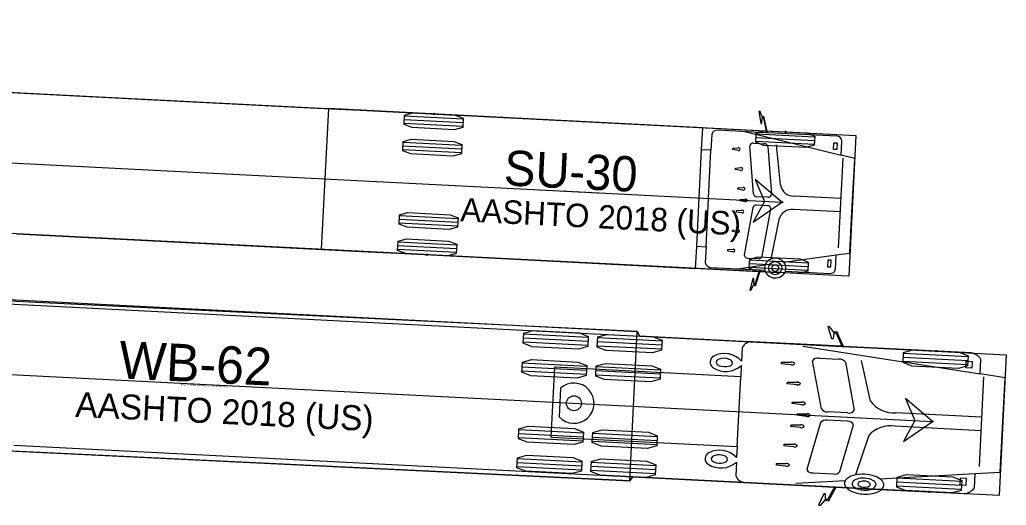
# Model space of a CAD drawing. Extents: x 260275 to 261282, y 610916 to 614143.
# Drawn here: x 261226.4 to 261282.5, y 611586.9 to 611614.4 of the extents above; entities that cross this region are included whole.
import ezdxf

# ---------------------------------------------------------------- set-up
doc = ezdxf.new("R2010")
doc.units = 0
doc.layers.add('UT_X_Water_Cells', color=7, linetype='Continuous')

msp = doc.modelspace()

# ---------------------------------------------------------------- linework, layer by layer
at = {"layer": 'UT_X_Water_Cells'}
for p, q in [((261066.343, 611614.434), (261269.731, 611604.069)), ((261251.604, 611608.581), (261248.275, 611608.751)), ((261251.615, 611608.789), (261248.286, 611608.959)), ((261251.594, 611608.373), (261248.265, 611608.543)), ((261267.627, 611608.081), (261273.094, 611606.736)), ((261271.568, 611607.354), (261268.239, 611607.524)), ((261271.578, 611607.563), (261268.249, 611607.732)), ((261271.589, 611607.771), (261268.26, 611607.94)), ((261251.517, 611606.875), (261248.188, 611607.044)), ((261251.528, 611607.083), (261248.199, 611607.253)), ((261251.539, 611607.291), (261248.21, 611607.461)), ((261264.884, 611601.566), (261265.164, 611607.051)), ((261265.415, 611601.539), (261265.695, 611607.024)), ((261266.938, 611607.056), (261266.942, 611607.139)), ((261267.236, 611607.005), (261266.938, 611607.056)), ((261266.942, 611607.139), (261267.244, 611607.159)), ((261268.116, 611604.541), (261267.902, 611607.25)), ((261268.113, 611607.421), (261268.729, 611607.389)), ((261268.923, 611607.228), (261269.137, 611604.519)), ((261269.651, 611605.056), (261269.422, 611607.334)), ((261272.654, 611607.07), (261272.673, 611607.448)), ((261272.848, 611607.06), (261272.654, 611607.07)), ((261272.673, 611607.448), (261272.867, 611607.438)), ((261272.867, 611607.438), (261272.848, 611607.06)), ((261272.949, 611601.482), (261273.209, 611606.58)), ((261267.091, 611605.93), (261267.096, 611606.012)), ((261267.403, 611605.879), (261267.091, 611605.93)), ((261267.096, 611606.012), (261267.41, 611606.033)), ((261267.217, 611604.805), (261267.221, 611604.887)), ((261267.514, 611604.754), (261267.217, 611604.805)), ((261267.221, 611604.887), (261267.522, 611604.908)), ((261267.352, 611604.149), (261267.356, 611604.231)), ((261267.649, 611604.098), (261267.352, 611604.149)), ((261267.356, 611604.231), (261267.657, 611604.252)), ((261268.926, 611604.348), (261268.31, 611604.379)), ((261273.091, 611604.281), (261270.427, 611604.417)), ((261267.151, 611603.51), (261267.155, 611603.592)), ((261267.155, 611603.592), (261267.456, 611603.613)), ((261268.076, 611603.763), (261267.588, 611601.09)), ((261268.902, 611603.873), (261268.286, 611603.904)), ((261268.606, 611601.008), (261269.094, 611603.681)), ((261273.052, 611603.516), (261270.388, 611603.652)), ((261251.316, 611602.922), (261247.987, 611603.091)), ((261251.326, 611603.13), (261247.997, 611603.299)), ((261267.448, 611603.459), (261267.151, 611603.51)), ((261269.551, 611603.095), (261269.089, 611600.84)), ((261251.305, 611602.713), (261247.976, 611602.883)), ((261266.912, 611602.403), (261266.916, 611602.486)), ((261266.916, 611602.486), (261267.217, 611602.506)), ((261267.209, 611602.352), (261266.912, 611602.403)), ((261251.229, 611601.215), (261247.9, 611601.385)), ((261251.239, 611601.423), (261247.91, 611601.593)), ((261251.25, 611601.632), (261247.921, 611601.801)), ((261266.645, 611601.298), (261266.649, 611601.381)), ((261266.649, 611601.381), (261266.95, 611601.401)), ((261266.942, 611601.247), (261266.645, 611601.298)), ((261267.78, 611600.899), (261268.396, 611600.867)), ((261271.224, 611600.613), (261267.895, 611600.783)), ((261269.839, 611600.657), (261272.805, 611601.073)), ((261272.334, 611600.786), (261272.315, 611600.408)), ((261272.528, 611600.776), (261272.334, 611600.786)), ((261267.23, 611600.291), (261268.764, 611600.506)), ((261271.203, 611600.197), (261267.874, 611600.367)), ((261271.214, 611600.405), (261267.885, 611600.575)), ((261272.315, 611600.408), (261272.508, 611600.398)), ((261272.508, 611600.398), (261272.528, 611600.776)), ((261269.929, 611600.154), (261272.448, 611600.025)), ((261137.985, 611598.767), (261278.274, 611591.618)), ((261258.713, 611596.159), (261255.051, 611596.345)), ((261258.724, 611596.388), (261255.062, 611596.574)), ((261262.919, 611596.175), (261259.257, 611596.361)), ((261272.689, 611596.668), (261272.674, 611596.689)), ((261272.687, 611596.642), (261272.689, 611596.668)), ((261258.701, 611595.93), (261255.039, 611596.117)), ((261262.896, 611595.717), (261259.234, 611595.903)), ((261262.907, 611595.946), (261259.245, 611596.132)), ((261267.474, 611595.822), (261267.434, 611595.048)), ((261270.921, 611595.897), (261280.988, 611594.319)), ((261271.839, 611595.215), (261272.968, 611595.157)), ((261280.285, 611595.062), (261276.623, 611595.248)), ((261280.296, 611595.291), (261276.635, 611595.477)), ((261258.629, 611594.511), (261254.967, 611594.698)), ((261258.641, 611594.74), (261254.979, 611594.926)), ((261262.835, 611594.527), (261259.173, 611594.713)), ((261269.703, 611594.899), (261269.707, 611594.981)), ((261270.25, 611594.835), (261269.703, 611594.899)), ((261269.707, 611594.981), (261270.258, 611594.989)), ((261271.966, 611592.329), (261271.459, 611595.052)), ((261273.33, 611594.987), (261273.837, 611592.263)), ((261274.756, 611592.779), (261274.239, 611595.073)), ((261280.273, 611594.833), (261276.611, 611595.019)), ((261280.169, 611594.671), (261280.189, 611595.049)), ((261280.525, 611594.653), (261280.169, 611594.671)), ((261280.189, 611595.049), (261280.544, 611595.031)), ((261280.544, 611595.031), (261280.525, 611594.653)), ((261258.617, 611594.282), (261254.955, 611594.469)), ((261262.812, 611594.069), (261259.15, 611594.255)), ((261262.823, 611594.298), (261259.162, 611594.484)), ((261267.187, 611590.192), (261267.389, 611594.161)), ((261280.946, 611589.059), (261281.205, 611594.158)), ((261282.132, 611588.733), (261282.405, 611594.096)), ((261257.146, 611593.502), (261257.064, 611591.888)), ((261270.031, 611593.764), (261270.035, 611593.846)), ((261270.603, 611593.699), (261270.031, 611593.764)), ((261270.035, 611593.846), (261270.611, 611593.853)), ((261270.308, 611592.631), (261270.313, 611592.713)), ((261270.855, 611592.567), (261270.308, 611592.631)), ((261270.313, 611592.713), (261270.863, 611592.721)), ((261270.584, 611591.968), (261270.588, 611592.05)), ((261271.131, 611591.904), (261270.584, 611591.968)), ((261270.588, 611592.05), (261271.138, 611592.058)), ((261273.458, 611592.101), (261272.328, 611592.158)), ((261281.088, 611591.858), (261276.203, 611592.106)), ((261270.242, 611591.336), (261270.247, 611591.418)), ((261270.79, 611591.272), (261270.242, 611591.336)), ((261270.247, 611591.418), (261270.797, 611591.426)), ((261271.927, 611591.551), (261271.146, 611588.893)), ((261273.434, 611591.626), (261272.304, 611591.683)), ((261273.013, 611588.768), (261273.794, 611591.426)), ((261281.05, 611591.093), (261276.164, 611591.342)), ((261258.437, 611590.733), (261254.775, 611590.919)), ((261258.448, 611590.962), (261254.786, 611591.148)), ((261262.631, 611590.519), (261258.969, 611590.706)), ((261262.643, 611590.748), (261258.981, 611590.935)), ((261274.656, 611590.819), (261273.905, 611588.579)), ((261258.425, 611590.504), (261254.763, 611590.69)), ((261262.62, 611590.291), (261258.958, 611590.477)), ((261269.852, 611590.237), (261269.856, 611590.32)), ((261270.399, 611590.173), (261269.852, 611590.237)), ((261269.856, 611590.32), (261270.407, 611590.328)), ((261258.341, 611588.856), (261254.679, 611589.042)), ((261258.353, 611589.085), (261254.691, 611589.271)), ((261258.364, 611589.314), (261254.703, 611589.5)), ((261262.547, 611588.872), (261258.885, 611589.058)), ((261262.559, 611589.1), (261258.897, 611589.287)), ((261267.142, 611589.306), (261267.103, 611588.531)), ((261269.41, 611589.141), (261269.414, 611589.223)), ((261269.957, 611589.077), (261269.41, 611589.141)), ((261269.414, 611589.223), (261269.965, 611589.231)), ((261262.536, 611588.643), (261258.874, 611588.829)), ((261271.507, 611588.692), (261272.636, 611588.635)), ((261275.286, 611588.364), (261280.7, 611588.655)), ((261270.524, 611588.107), (261273.324, 611588.258)), ((261279.913, 611587.759), (261276.251, 611587.945)), ((261279.925, 611587.988), (261276.263, 611588.174)), ((261279.937, 611588.216), (261276.275, 611588.403)), ((261279.85, 611588.388), (261279.83, 611588.01)), ((261279.83, 611588.01), (261280.186, 611587.991)), ((261280.205, 611588.37), (261279.85, 611588.388)), ((261280.186, 611587.991), (261280.205, 611588.37)), ((261275.389, 611587.759), (261280.084, 611587.521)), ((261272.206, 611587.16), (261272.188, 611587.141)), ((261272.206, 611587.186), (261272.206, 611587.16))]:
    msp.add_line(p, q, dxfattribs=at)
for points in [[(261156.1, 611613.904), (261198.699, 611611.699), (261273.93, 611607.86), (261273.523, 611599.87), (261188.635, 611604.191), (261146.014, 611606.327)], [(261223.331, 611610.44), (261226.66, 611610.27), (261229.989, 611610.1), (261233.317, 611609.931), (261236.646, 611609.761), (261239.975, 611609.591), (261243.304, 611609.421), (261246.632, 611609.252), (261249.961, 611609.082)], [(261223.333, 611610.439), (261226.662, 611610.269), (261229.99, 611610.099), (261233.319, 611609.93), (261236.648, 611609.76), (261239.976, 611609.59), (261243.305, 611609.421), (261246.634, 611609.251), (261249.963, 611609.081), (261253.291, 611608.912), (261256.62, 611608.742), (261259.949, 611608.572), (261263.278, 611608.403), (261266.606, 611608.233), (261269.935, 611608.064)], [(261265.741, 611607.922), (261265.695, 611607.027), (261265.691, 611607.024), (261265.165, 611607.051), (261265.165, 611607.062), (261265.228, 611608.304), (261243.969, 611609.387), (261243.765, 611605.393), (261243.561, 611601.398), (261264.82, 611600.314), (261264.884, 611601.555), (261264.885, 611601.566), (261265.412, 611601.539), (261265.415, 611601.536), (261265.369, 611600.641)], [(261268.651, 611608.91), (261268.604, 611608.913), (261268.603, 611608.913), (261268.487, 611609.214), (261268.422, 611609.218), (261268.422, 611609.215), (261268.528, 611608.553), (261268.529, 611608.549), (261268.584, 611608.547), (261268.585, 611608.549), (261268.61, 611608.866), (261268.61, 611608.866), (261268.654, 611608.863)], [(261268.674, 611608.851), (261268.674, 611608.851), (261268.851, 611608.023), (261268.839, 611608.019), (261266.069, 611608.161)], [(261272.845, 611607.815), (261268.917, 611608.015), (261268.906, 611608.023), (261268.722, 611608.865), (261268.722, 611608.866)], [(261272.764, 611600.263), (261272.805, 611601.069), (261272.81, 611601.074), (261273.587, 611601.183), (261273.592, 611601.225), (261273.726, 611603.865), (261273.861, 611606.505), (261273.861, 611606.547), (261273.098, 611606.735), (261273.094, 611606.74), (261273.135, 611607.546)], [(261269.731, 611604.069), (261268.209, 611605.365), (261268.733, 611604.12), (261268.085, 611602.934), (261269.731, 611604.069)], [(261226.252, 611602.281), (261229.581, 611602.111), (261232.91, 611601.941), (261236.239, 611601.771), (261239.567, 611601.601), (261242.896, 611601.432), (261246.225, 611601.262), (261249.554, 611601.092)], [(261226.253, 611602.279), (261229.582, 611602.11), (261232.911, 611601.94), (261236.24, 611601.77), (261239.569, 611601.601), (261242.897, 611601.431), (261246.226, 611601.261), (261249.555, 611601.092), (261252.884, 611600.922), (261256.213, 611600.752), (261259.541, 611600.583), (261262.87, 611600.413), (261266.199, 611600.244), (261269.528, 611600.074)], [(261170.375, 611601.234), (261181.049, 611600.761), (261202.389, 611599.731), (261261.501, 611596.733), (261261.634, 611596.472), (261282.472, 611595.409), (261282.066, 611587.42), (261261.234, 611588.48), (261261.092, 611588.243), (261197.652, 611591.285), (261176.331, 611592.251), (261165.672, 611592.71)], [(261265.672, 611600.371), (261268.442, 611600.229), (261268.454, 611600.224), (261268.193, 611599.419), (261268.193, 611599.419)], [(261268.239, 611599.399), (261268.239, 611599.4), (261268.508, 611600.219), (261268.52, 611600.225), (261268.748, 611600.214)], [(261268.172, 611599.409), (261268.128, 611599.41), (261268.127, 611599.411), (261268.135, 611599.728), (261268.135, 611599.731), (261268.079, 611599.733), (261268.078, 611599.731), (261267.906, 611599.083), (261267.905, 611599.08), (261267.97, 611599.076), (261268.117, 611599.364), (261268.117, 611599.364), (261268.164, 611599.363)], [(261213.219, 611590.573), (261213.218, 611590.55), (261261.092, 611588.243), (261261.296, 611592.488), (261261.501, 611596.733), (261213.627, 611599.04), (261213.626, 611599.018)], [(261223.157, 611598.432), (261226.49, 611598.262), (261229.823, 611598.092), (261233.156, 611597.922), (261236.488, 611597.753), (261239.821, 611597.583), (261243.154, 611597.413), (261246.486, 611597.243), (261249.819, 611597.073), (261253.151, 611596.903), (261256.484, 611596.733), (261259.816, 611596.564), (261263.148, 611596.394), (261266.481, 611596.224), (261269.813, 611596.054), (261273.145, 611595.884), (261276.478, 611595.715), (261278.477, 611595.613)], [(261272.761, 611596.684), (261272.674, 611596.689), (261272.448, 611596.996), (261272.328, 611597.002), (261272.552, 611596.328), (261272.654, 611596.323), (261272.687, 611596.642), (261272.768, 611596.638)], [(261272.805, 611596.624), (261272.805, 611596.624), (261273.123, 611595.885), (261268.048, 611596.143)], [(261280.49, 611595.51), (261273.223, 611595.88), (261272.892, 611596.637)], [(261267.421, 611594.791), (261267.389, 611594.161), (261256.803, 611594.7), (261256.601, 611590.731), (261267.187, 611590.192), (261267.155, 611589.563)], [(261282.132, 611588.733), (261282.405, 611594.096), (261280.988, 611594.319), (261281.029, 611595.132)], [(261278.274, 611591.618), (261276.751, 611592.914), (261277.275, 611591.669), (261276.627, 611590.483), (261278.274, 611591.618)], [(261226.091, 611590.272), (261229.422, 611590.102), (261232.754, 611589.932), (261236.086, 611589.763), (261239.418, 611589.593), (261242.75, 611589.423), (261246.082, 611589.253), (261249.414, 611589.083), (261252.746, 611588.914), (261256.078, 611588.744), (261259.41, 611588.574), (261262.742, 611588.404), (261266.075, 611588.234), (261269.407, 611588.064), (261272.739, 611587.895), (261276.071, 611587.725), (261278.071, 611587.623)], [(261280.659, 611587.842), (261280.7, 611588.655), (261282.12, 611588.732)], [(261267.642, 611588.153), (261272.717, 611587.895), (261272.325, 611587.192), (261272.325, 611587.192)], [(261272.41, 611587.171), (261272.816, 611587.89), (261273.389, 611587.861)], [(261272.287, 611587.183), (261272.206, 611587.186), (261272.206, 611587.507), (261272.103, 611587.512), (261271.812, 611586.864), (261271.932, 611586.858), (261272.188, 611587.141), (261272.275, 611587.137)]]:
    msp.add_lwpolyline(points, dxfattribs=at)
for points in [[(261251.618, 611608.841), (261251.591, 611608.321), (261251.117, 611608.188), (261248.72, 611608.311), (261248.262, 611608.491), (261248.289, 611609.01), (261248.763, 611609.143), (261251.16, 611609.021)], [(261271.592, 611607.822), (261271.565, 611607.303), (261271.091, 611607.17), (261268.694, 611607.292), (261268.236, 611607.473), (261268.263, 611607.992), (261268.737, 611608.125), (261271.134, 611608.002)], [(261251.541, 611607.342), (261251.515, 611606.823), (261251.041, 611606.69), (261248.644, 611606.813), (261248.186, 611606.993), (261248.212, 611607.512), (261248.686, 611607.645), (261251.083, 611607.523)], [(261269.731, 611604.069), (261268.209, 611605.365), (261268.733, 611604.12), (261268.085, 611602.934)], [(261251.329, 611603.181), (261251.303, 611602.662), (261250.829, 611602.529), (261248.432, 611602.651), (261247.974, 611602.832), (261248, 611603.351), (261248.474, 611603.484), (261250.871, 611603.361)], [(261251.253, 611601.683), (261251.226, 611601.164), (261250.752, 611601.031), (261248.355, 611601.153), (261247.897, 611601.334), (261247.924, 611601.853), (261248.398, 611601.986), (261250.795, 611601.863)], [(261271.227, 611600.665), (261271.2, 611600.146), (261270.726, 611600.013), (261268.329, 611600.135), (261267.871, 611600.315), (261267.898, 611600.835), (261268.372, 611600.967), (261270.769, 611600.845)], [(261258.727, 611596.445), (261258.698, 611595.874), (261258.177, 611595.728), (261255.54, 611595.862), (261255.036, 611596.06), (261255.065, 611596.631), (261255.587, 611596.777), (261258.223, 611596.643)], [(261262.922, 611596.231), (261262.893, 611595.66), (261262.371, 611595.514), (261259.735, 611595.648), (261259.231, 611595.846), (261259.26, 611596.418), (261259.781, 611596.564), (261262.418, 611596.43)], [(261280.299, 611595.347), (261280.27, 611594.776), (261279.749, 611594.63), (261277.112, 611594.764), (261276.608, 611594.962), (261276.637, 611595.534), (261277.159, 611595.68), (261279.795, 611595.546)], [(261258.643, 611594.797), (261258.614, 611594.226), (261258.093, 611594.08), (261255.456, 611594.214), (261254.952, 611594.412), (261254.981, 611594.983), (261255.503, 611595.129), (261258.139, 611594.995)], [(261262.838, 611594.584), (261262.809, 611594.012), (261262.287, 611593.866), (261259.651, 611594), (261259.147, 611594.199), (261259.176, 611594.77), (261259.697, 611594.916), (261262.334, 611594.782)], [(261278.274, 611591.618), (261276.751, 611592.914), (261277.275, 611591.669), (261276.627, 611590.483)], [(261258.451, 611591.018), (261258.422, 611590.447), (261257.901, 611590.301), (261255.264, 611590.435), (261254.76, 611590.634), (261254.789, 611591.205), (261255.311, 611591.351), (261257.947, 611591.217)], [(261262.646, 611590.805), (261262.617, 611590.234), (261262.095, 611590.088), (261259.459, 611590.222), (261258.955, 611590.42), (261258.984, 611590.991), (261259.505, 611591.137), (261262.142, 611591.003)], [(261258.367, 611589.371), (261258.338, 611588.799), (261257.817, 611588.653), (261255.18, 611588.787), (261254.676, 611588.986), (261254.705, 611589.557), (261255.227, 611589.703), (261257.863, 611589.569)], [(261262.562, 611589.157), (261262.533, 611588.586), (261262.011, 611588.44), (261259.375, 611588.574), (261258.871, 611588.772), (261258.9, 611589.344), (261259.421, 611589.49), (261262.058, 611589.355)], [(261279.939, 611588.273), (261279.91, 611587.702), (261279.389, 611587.556), (261276.752, 611587.69), (261276.248, 611587.888), (261276.278, 611588.459), (261276.799, 611588.606), (261279.436, 611588.471)]]:
    msp.add_lwpolyline(points, close=True, dxfattribs=at)
for centre, radius in [((261249.961, 611609.082), 0.0417), ((261269.935, 611608.064), 0.0417), ((261269.731, 611604.069), 0.0417), ((261249.554, 611601.092), 0.0417), ((261269.346, 611600.329), 0.374), ((261269.346, 611600.329), 0.193), ((261269.528, 611600.074), 0.0417), ((261278.477, 611595.613), 0.0417), ((261257.912, 611592.651), 0.424), ((261278.274, 611591.618), 0.0417), ((261278.071, 611587.623), 0.0417)]:
    msp.add_circle(centre, radius, dxfattribs=at)
for centre, radius, start, end in [((261268.686, 611608.887), 0.0418, 329.5734, 146.5883), ((261268.686, 611608.893), 0.0434, 222.4952, 253.168), ((261266.052, 611607.838), 0.323, 87.0815, 164.9299), ((261272.853, 611607.534), 0.282, 2.6299, 91.7093), ((261267.259, 611607.093), 0.0909, 255.3624, 349.5976), ((261267.257, 611607.069), 0.091, 4.601, 98.7649), ((261268.086, 611607.238), 0.184, 81.6176, 176.4889), ((261268.733, 611607.197), 0.193, 9.2239, 91.1384), ((261267.412, 611605.967), 0.0909, 255.3624, 349.5976), ((261267.411, 611605.943), 0.091, 4.601, 98.7649), ((261267.537, 611604.842), 0.0909, 255.3624, 349.5976), ((261267.536, 611604.818), 0.091, 4.601, 98.7649), ((261270.412, 611605.189), 0.773, 189.9719, 271.0561), ((261267.672, 611604.186), 0.091, 255.398, 349.5619), ((261267.671, 611604.162), 0.091, 4.601, 98.7649), ((261268.306, 611604.572), 0.193, 189.219, 271.1433), ((261268.953, 611604.53), 0.184, 261.6232, 356.4833), ((261267.47, 611603.523), 0.0909, 4.5654, 98.8006), ((261268.262, 611603.713), 0.193, 83.0196, 164.944), ((261268.91, 611603.689), 0.184, 357.6796, 92.5397), ((261270.295, 611602.885), 0.773, 83.1068, 164.191), ((261267.471, 611603.547), 0.091, 255.398, 349.5619), ((261267.231, 611602.417), 0.0909, 4.5654, 98.8006), ((261267.232, 611602.44), 0.091, 255.398, 349.5619), ((261266.964, 611601.312), 0.0909, 4.5654, 98.8006), ((261266.965, 611601.335), 0.091, 255.398, 349.5619), ((261267.772, 611601.083), 0.184, 177.674, 272.5453), ((261268.42, 611601.058), 0.193, 263.0246, 344.9391), ((261269.335, 611600.26), 0.63, 86.4363, 138.8391), ((261269.35, 611600.26), 0.629, 39.1271, 87.8164), ((261265.688, 611600.693), 0.323, 189.2331, 267.0815), ((261269.259, 611600.333), 0.524, 139.3405, 193.1406), ((261269.432, 611600.324), 0.526, 341.0266, 39.2726), ((261272.485, 611600.304), 0.282, 262.4536, 351.5331), ((261269.349, 611600.396), 0.628, 196.8348, 337.3265), ((261268.201, 611599.382), 0.0418, 207.5746, 24.5896), ((261268.201, 611599.376), 0.0434, 100.995, 131.6678), ((261272.823, 611596.573), 0.127, 54.9831, 119.1923), ((261272.823, 611596.733), 0.11, 240.0352, 260.1435), ((261272.881, 611596.658), 0.0244, 297.9553, 51.2697), ((261267.989, 611595.575), 0.571, 84.0031, 154.3947), ((261266.035, 611594.99), 0.387, 118.5832, 235.5922), ((261266.454, 611594.129), 1.344, 43.1231, 116.6779), ((261266.425, 611594.344), 0.86, 68.6537, 108.6231), ((261271.751, 611594.89), 0.334, 78.2249, 150.8228), ((261280.347, 611594.732), 0.792, 30.3988, 79.5543), ((261266.539, 611595.804), 1.344, 237.4975, 311.0523), ((261266.207, 611594.938), 0.228, 104.39, 166.2848), ((261266.243, 611595.042), 0.262, 190.8797, 257.4049), ((261266.487, 611595.612), 0.879, 249.9556, 284.5508), ((261266.684, 611595.007), 0.247, 275.4913, 345.3704), ((261266.643, 611594.871), 0.29, 14.732, 70.892), ((261270.301, 611595.02), 0.192, 254.5101, 322.0394), ((261270.29, 611594.8), 0.192, 32.1634, 99.638), ((261273, 611594.755), 0.403, 35.0874, 94.5454), ((261257.912, 611592.654), 1.143, 222.0877, 132.0877), ((261270.63, 611593.885), 0.192, 254.5101, 322.0394), ((261270.618, 611593.664), 0.192, 32.1634, 99.638), ((261270.907, 611592.752), 0.192, 254.5101, 322.0394), ((261270.895, 611592.532), 0.192, 32.1634, 99.638), ((261276.079, 611593.733), 1.631, 215.7635, 274.3543), ((261271.182, 611592.089), 0.192, 254.5374, 322.012), ((261271.171, 611591.869), 0.192, 32.1634, 99.638), ((261272.292, 611592.555), 0.397, 214.8489, 273.0119), ((261273.545, 611592.435), 0.342, 258.6895, 328.616), ((261270.841, 611591.457), 0.192, 254.5374, 322.012), ((261270.83, 611591.237), 0.192, 32.136, 99.6653), ((261272.228, 611591.292), 0.397, 81.1635, 139.3265), ((261273.486, 611591.285), 0.342, 25.5594, 95.4859), ((261275.876, 611589.737), 1.631, 79.8211, 138.4119), ((261270.45, 611590.359), 0.192, 254.5374, 322.012), ((261270.439, 611590.138), 0.192, 32.136, 99.6653), ((261265.748, 611589.505), 0.383, 117.5585, 236.6169), ((261266.174, 611588.644), 1.344, 43.1231, 116.6779), ((261265.957, 611589.432), 0.262, 96.7705, 163.2957), ((261266.142, 611588.84), 0.879, 69.6246, 104.2198), ((261266.4, 611589.422), 0.247, 8.805, 78.6841), ((261266.26, 611590.319), 1.344, 237.4975, 311.0523), ((261265.932, 611589.539), 0.228, 187.8906, 249.7854), ((261266.209, 611590.108), 0.86, 245.5523, 285.5217), ((261266.372, 611589.562), 0.29, 283.2834, 339.4434), ((261270.008, 611589.263), 0.192, 254.5374, 322.012), ((261269.997, 611589.042), 0.192, 32.136, 99.6653), ((261267.64, 611588.725), 0.571, 199.7807, 270.1723), ((261271.452, 611589.025), 0.334, 203.3526, 275.9505), ((261272.709, 611589.032), 0.403, 259.63, 319.088), ((261273.955, 611587.768), 0.799, 102.8871, 142.1548), ((261274.311, 611586.607), 2.012, 86.7291, 105.412), ((261274.333, 611586.569), 2.049, 71.4687, 87.394), ((261274.667, 611587.486), 1.074, 48.5443, 72.8132), ((261273.577, 611588.096), 0.301, 147.319, 231.2173), ((261273.911, 611588.078), 0.199, 130.891, 231.5303), ((261274.318, 611587.489), 0.914, 83.9221, 125.9801), ((261274.37, 611588.626), 0.913, 230.3973, 270.6576), ((261274.165, 611588.068), 0.12, 102.0638, 247.5418), ((261274.426, 611588.509), 0.631, 240.896, 283.6965), ((261274.376, 611587.616), 0.617, 79.3753, 112.5661), ((261274.381, 611587.3), 1.098, 60.3535, 88.2461), ((261274.495, 611587.953), 0.27, 18.2366, 90.9804), ((261274.544, 611588.113), 0.22, 278.0976, 339.7958), ((261274.697, 611588.152), 0.407, 278.3183, 341.1227), ((261274.815, 611588.01), 0.268, 2.1603, 65.838), ((261275.138, 611587.995), 0.38, 0.4181, 50.9416), ((261275.191, 611588.021), 0.328, 307.176, 356.0804), ((261274.076, 611588.479), 0.924, 221.9848, 258.263), ((261274.485, 611589.696), 2.204, 254.2868, 273.9219), ((261274.451, 611588.945), 1.234, 266.7174, 284.2995), ((261274.53, 611589.225), 1.731, 273.4728, 288.6706), ((261274.891, 611588.277), 0.719, 285.6181, 313.8751), ((261280.02, 611588.309), 0.792, 274.6211, 323.7766), ((261272.348, 611587.241), 0.127, 234.9831, 299.1923), ((261272.332, 611587.082), 0.11, 94.0319, 114.1402), ((261272.397, 611587.151), 0.0244, 302.9057, 56.2201)]:
    msp.add_arc(centre, radius, start, end, dxfattribs=at)
for centre, major_axis, start_param, end_param in [((261272.827, 611596.661), (-0.0781, 0.004), 5.756759, 7.026061), ((261272.827, 611596.661), (0.0781, -0.004), 4.442794, 5.713538), ((261272.344, 611587.153), (0.0781, -0.004), 2.398717, 3.668019), ((261272.344, 611587.153), (-0.0781, 0.004), 3.71124, 4.981984)]:
    msp.add_ellipse(centre, major_axis=major_axis, ratio=0.5, start_param=start_param, end_param=end_param, dxfattribs=at)

# ---------------------------------------------------------------- texts
for s, height, rotation, p in [('SU-30', 2, 357.0815, (261253.903, 611605.036)), ('(c) 2023 Transoft Solutions, Inc. All rights reserved.', 0.08, 357.0815, (261257.108, 611604.672)), ('AASHTO 2018 (US)', 1.33333, 357.0815, (261251.439, 611602.992)), ('WB-62', 2.125, 357.241, (261232.026, 611594.069)), ('(c) 2023 Transoft Solutions, Inc. All rights reserved.', 0.085, 357.241, (261235.584, 611593.685)), ('AASHTO 2018 (US)', 1.41667, 357.241, (261229.565, 611591.883))]:
    msp.add_text(s, height=height, rotation=rotation, dxfattribs=at).set_placement(p)

doc.saveas('drawing.dxf')
